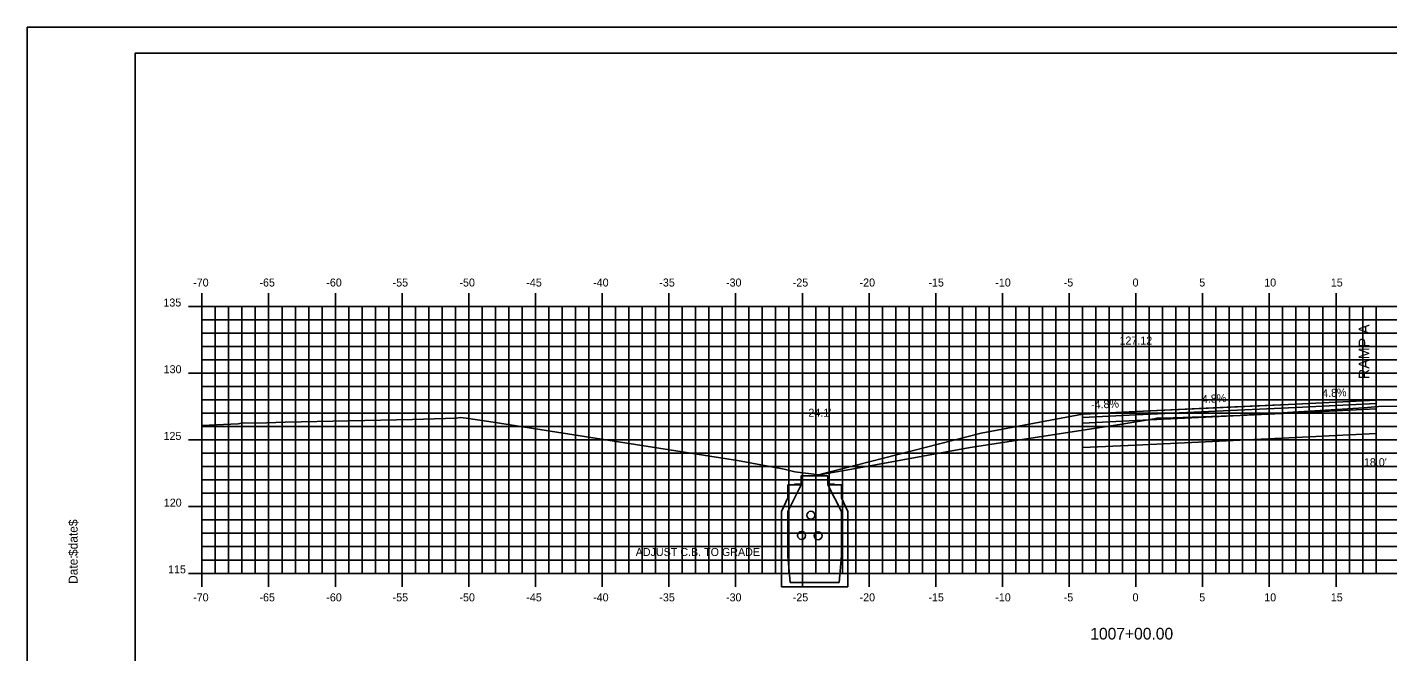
# Model space of a CAD drawing. Extents: x 851517 to 851688, y 365624 to 365734.
# Drawn here: x 851516.7 to 851618.7, y 365687.1 to 365734 of the extents above; entities that cross this region are included whole.
import ezdxf

# ---------------------------------------------------------------- set-up
doc = ezdxf.new("R2010")
doc.units = 0
for name, color, linetype in [('ANNOTATION', 7, 'Continuous'), ('BORDER', 7, 'Continuous'), ('D_Roadway_Centerline', 7, 'Continuous'), ('D_Roadway_Centerline_Text', 7, 'Continuous'), ('D_Roadway_Edge_Shoulder', 7, 'Continuous'), ('D_Roadway_Edge_TW', 7, 'Continuous'), ('D_Roadway_FinishedGrade', 7, 'Continuous'), ('D_Roadway_Pavement', 7, 'Continuous'), ('D_Roadway_SubGrade', 7, 'Continuous'), ('D_Text_Standard', 7, 'Continuous'), ('H_V ANNOTATION', 7, 'Continuous'), ('M_Roadway_Centerline', 7, 'Continuous'), ('MAJOR', 7, 'Continuous'), ('MINOR', 7, 'Continuous'), ('PLOT BOUNDARY', 7, 'Continuous'), ('S_Drainage_CB', 7, 'Continuous'), ('S_Drainage_Invert', 7, 'Continuous'), ('S_Roadway_Centerline', 7, 'Continuous')]:
    doc.layers.add(name, color=color, linetype=linetype)

msp = doc.modelspace()

# ---------------------------------------------------------------- linework, layer by layer
at = {"layer": 'BORDER'}
msp.add_lwpolyline([(851524.77, 365627.03), (851684.77, 365627.03), (851684.77, 365732.03), (851524.77, 365732.03)], close=True, dxfattribs=at)
at = {"layer": 'D_Roadway_Centerline'}
for points in [[(851595.77, 365704.96), (851598.1, 365705.07), (851599.76, 365705.15), (851599.77, 365705.15), (851606.61, 365705.48), (851611.77, 365705.72), (851611.77, 365705.72), (851617.78, 365706.01)], [(851595.77, 365704.96), (851588.17, 365703.54), (851575.68, 365700.33)]]:
    msp.add_lwpolyline(points, dxfattribs=at)
at = {"layer": 'D_Roadway_Edge_Shoulder'}
msp.add_lwpolyline([(851599.77, 365705.15), (851595.77, 365704.96), (851595.77, 365704.71), (851599.77, 365704.9)], close=True, dxfattribs=at)
at = {"layer": 'D_Roadway_Edge_TW'}
for points in [[(851599.77, 365705.15), (851611.77, 365705.72), (851611.77, 365705.47), (851599.77, 365704.9)], [(851611.77, 365705.72), (851617.78, 365706.01), (851617.78, 365705.76), (851611.77, 365705.47)]]:
    msp.add_lwpolyline(points, close=True, dxfattribs=at)
at = {"layer": 'D_Roadway_FinishedGrade'}
for p, q in [((851599.77, 365705.15), (851599.77, 365704.9)), ((851599.77, 365705.15), (851599.77, 365704.9)), ((851611.77, 365705.72), (851611.77, 365705.47)), ((851617.78, 365706.01), (851617.78, 365705.76)), ((851617.78, 365706.01), (851617.78, 365705.76)), ((851595.77, 365704.96), (851595.77, 365704.71)), ((851595.77, 365704.96), (851595.77, 365704.71))]:
    msp.add_line(p, q, dxfattribs=at)
at = {"layer": 'D_Roadway_Pavement'}
for points in [[(851599.77, 365704.9), (851611.77, 365705.47), (851611.77, 365705.06), (851599.77, 365704.48)], [(851611.77, 365705.47), (851617.78, 365705.76), (851617.78, 365705.35), (851611.77, 365705.06)], [(851599.77, 365704.9), (851595.77, 365704.71), (851595.77, 365704.29), (851599.77, 365704.48)]]:
    msp.add_lwpolyline(points, close=True, dxfattribs=at)
at = {"layer": 'D_Roadway_SubGrade'}
msp.add_line((851617.78, 365712.51), (851617.78, 365703.51), dxfattribs=at)
for points in [[(851611.77, 365705.06), (851617.78, 365705.35), (851617.78, 365703.51), (851611.77, 365703.22)], [(851599.77, 365704.48), (851595.77, 365704.29), (851595.77, 365704.79), (851595.77, 365704.96), (851595.77, 365702.46), (851599.77, 365702.65)], [(851599.77, 365704.48), (851611.77, 365705.06), (851611.77, 365703.22), (851599.77, 365702.65)]]:
    msp.add_lwpolyline(points, close=True, dxfattribs=at)
at = {"layer": 'MAJOR'}
for p, q in [((851529.77, 365714.03), (851529.77, 365713.03)), ((851534.77, 365714.03), (851534.77, 365713.03)), ((851539.77, 365714.03), (851539.77, 365713.03)), ((851544.77, 365714.03), (851544.77, 365713.03)), ((851549.77, 365714.03), (851549.77, 365713.03)), ((851554.77, 365714.03), (851554.77, 365713.03)), ((851559.77, 365714.03), (851559.77, 365713.03)), ((851564.77, 365714.03), (851564.77, 365713.03)), ((851569.77, 365714.03), (851569.77, 365713.03)), ((851574.77, 365714.03), (851574.77, 365713.03)), ((851579.77, 365714.03), (851579.77, 365713.03)), ((851584.77, 365714.03), (851584.77, 365713.03)), ((851589.77, 365714.03), (851589.77, 365713.03)), ((851594.77, 365714.03), (851594.77, 365713.03)), ((851599.77, 365714.03), (851599.77, 365713.03)), ((851604.77, 365714.03), (851604.77, 365713.03)), ((851609.77, 365714.03), (851609.77, 365713.03)), ((851614.77, 365714.03), (851614.77, 365713.03)), ((851528.76, 365713.03), (851529.77, 365713.03)), ((851529.77, 365713.03), (851669.77, 365713.03)), ((851529.77, 365693.03), (851529.77, 365713.03)), ((851529.77, 365693.03), (851529.77, 365713.03)), ((851529.77, 365713.03), (851669.77, 365713.03)), ((851534.77, 365693.03), (851534.77, 365713.03)), ((851539.77, 365693.03), (851539.77, 365713.03)), ((851544.77, 365693.03), (851544.77, 365713.03)), ((851549.77, 365693.03), (851549.77, 365713.03)), ((851554.77, 365693.03), (851554.77, 365713.03)), ((851559.77, 365693.03), (851559.77, 365713.03)), ((851564.77, 365693.03), (851564.77, 365713.03)), ((851569.77, 365693.03), (851569.77, 365713.03)), ((851574.77, 365693.03), (851574.77, 365713.03)), ((851579.77, 365693.03), (851579.77, 365713.03)), ((851584.77, 365693.03), (851584.77, 365713.03)), ((851589.77, 365693.03), (851589.77, 365713.03)), ((851594.77, 365693.03), (851594.77, 365713.03)), ((851599.77, 365693.03), (851599.77, 365713.03)), ((851604.77, 365693.03), (851604.77, 365713.03)), ((851609.77, 365693.03), (851609.77, 365713.03)), ((851614.77, 365693.03), (851614.77, 365713.03)), ((851528.76, 365708.03), (851529.77, 365708.03)), ((851529.77, 365708.03), (851669.77, 365708.03)), ((851528.76, 365703.03), (851529.77, 365703.03)), ((851529.77, 365703.03), (851669.77, 365703.03)), ((851528.76, 365698.03), (851529.77, 365698.03)), ((851529.77, 365698.03), (851669.77, 365698.03)), ((851528.76, 365693.03), (851529.77, 365693.03)), ((851529.77, 365693.03), (851669.77, 365693.03)), ((851529.77, 365693.03), (851669.77, 365693.03)), ((851529.77, 365692.02), (851529.77, 365693.03)), ((851534.77, 365692.02), (851534.77, 365693.03)), ((851539.77, 365692.02), (851539.77, 365693.03)), ((851544.77, 365692.02), (851544.77, 365693.03)), ((851549.77, 365692.02), (851549.77, 365693.03)), ((851554.77, 365692.02), (851554.77, 365693.03)), ((851559.77, 365692.02), (851559.77, 365693.03)), ((851564.77, 365692.02), (851564.77, 365693.03)), ((851569.77, 365692.02), (851569.77, 365693.03)), ((851574.77, 365692.02), (851574.77, 365693.03)), ((851579.77, 365692.02), (851579.77, 365693.03)), ((851584.77, 365692.02), (851584.77, 365693.03)), ((851589.77, 365692.02), (851589.77, 365693.03)), ((851594.77, 365692.02), (851594.77, 365693.03)), ((851599.77, 365692.02), (851599.77, 365693.03)), ((851604.77, 365692.02), (851604.77, 365693.03)), ((851609.77, 365692.02), (851609.77, 365693.03)), ((851614.77, 365692.02), (851614.77, 365693.03))]:
    msp.add_line(p, q, dxfattribs=at)
at = {"layer": 'MINOR'}
for p, q in [((851530.77, 365693.03), (851530.77, 365713.03)), ((851531.77, 365693.03), (851531.77, 365713.03)), ((851532.77, 365693.03), (851532.77, 365713.03)), ((851533.77, 365693.03), (851533.77, 365713.03)), ((851535.77, 365693.03), (851535.77, 365713.03)), ((851536.77, 365693.03), (851536.77, 365713.03)), ((851537.77, 365693.03), (851537.77, 365713.03)), ((851538.77, 365693.03), (851538.77, 365713.03)), ((851540.77, 365693.03), (851540.77, 365713.03)), ((851541.77, 365693.03), (851541.77, 365713.03)), ((851542.77, 365693.03), (851542.77, 365713.03)), ((851543.77, 365693.03), (851543.77, 365713.03)), ((851545.77, 365693.03), (851545.77, 365713.03)), ((851546.77, 365693.03), (851546.77, 365713.03)), ((851547.77, 365693.03), (851547.77, 365713.03)), ((851548.77, 365693.03), (851548.77, 365713.03)), ((851550.77, 365693.03), (851550.77, 365713.03)), ((851551.77, 365693.03), (851551.77, 365713.03)), ((851552.77, 365693.03), (851552.77, 365713.03)), ((851553.77, 365693.03), (851553.77, 365713.03)), ((851555.77, 365693.03), (851555.77, 365713.03)), ((851556.77, 365693.03), (851556.77, 365713.03)), ((851557.77, 365693.03), (851557.77, 365713.03)), ((851558.77, 365693.03), (851558.77, 365713.03)), ((851560.77, 365693.03), (851560.77, 365713.03)), ((851561.77, 365693.03), (851561.77, 365713.03)), ((851562.77, 365693.03), (851562.77, 365713.03)), ((851563.77, 365693.03), (851563.77, 365713.03)), ((851565.77, 365693.03), (851565.77, 365713.03)), ((851566.77, 365693.03), (851566.77, 365713.03)), ((851567.77, 365693.03), (851567.77, 365713.03)), ((851568.77, 365693.03), (851568.77, 365713.03)), ((851570.77, 365693.03), (851570.77, 365713.03)), ((851571.77, 365693.03), (851571.77, 365713.03)), ((851572.77, 365693.03), (851572.77, 365713.03)), ((851573.77, 365693.03), (851573.77, 365713.03)), ((851575.77, 365693.03), (851575.77, 365713.03)), ((851576.77, 365693.03), (851576.77, 365713.03)), ((851577.77, 365693.03), (851577.77, 365713.03)), ((851578.77, 365693.03), (851578.77, 365713.03)), ((851580.77, 365693.03), (851580.77, 365713.03)), ((851581.77, 365693.03), (851581.77, 365713.03)), ((851582.77, 365693.03), (851582.77, 365713.03)), ((851583.77, 365693.03), (851583.77, 365713.03)), ((851585.77, 365693.03), (851585.77, 365713.03)), ((851586.77, 365693.03), (851586.77, 365713.03)), ((851587.77, 365693.03), (851587.77, 365713.03)), ((851588.77, 365693.03), (851588.77, 365713.03)), ((851590.77, 365693.03), (851590.77, 365713.03)), ((851591.77, 365693.03), (851591.77, 365713.03)), ((851592.77, 365693.03), (851592.77, 365713.03)), ((851593.77, 365693.03), (851593.77, 365713.03)), ((851595.77, 365693.03), (851595.77, 365713.03)), ((851596.77, 365693.03), (851596.77, 365713.03)), ((851597.77, 365693.03), (851597.77, 365713.03)), ((851598.77, 365693.03), (851598.77, 365713.03)), ((851600.77, 365693.03), (851600.77, 365713.03)), ((851601.77, 365693.03), (851601.77, 365713.03)), ((851602.77, 365693.03), (851602.77, 365713.03)), ((851603.77, 365693.03), (851603.77, 365713.03)), ((851605.77, 365693.03), (851605.77, 365713.03)), ((851606.77, 365693.03), (851606.77, 365713.03)), ((851607.77, 365693.03), (851607.77, 365713.03)), ((851608.77, 365693.03), (851608.77, 365713.03)), ((851610.77, 365693.03), (851610.77, 365713.03)), ((851611.77, 365693.03), (851611.77, 365713.03)), ((851612.77, 365693.03), (851612.77, 365713.03)), ((851613.77, 365693.03), (851613.77, 365713.03)), ((851615.77, 365693.03), (851615.77, 365713.03)), ((851616.77, 365693.03), (851616.77, 365713.03)), ((851617.77, 365693.03), (851617.77, 365713.03)), ((851529.77, 365712.03), (851669.77, 365712.03)), ((851529.77, 365712.03), (851530.77, 365712.03)), ((851529.77, 365711.03), (851669.77, 365711.03)), ((851529.77, 365711.03), (851530.77, 365711.03)), ((851529.77, 365710.03), (851669.77, 365710.03)), ((851529.77, 365710.03), (851530.77, 365710.03)), ((851529.77, 365709.03), (851669.77, 365709.03)), ((851529.77, 365709.03), (851530.77, 365709.03)), ((851529.77, 365707.03), (851669.77, 365707.03)), ((851529.77, 365707.03), (851530.77, 365707.03)), ((851529.77, 365706.03), (851669.77, 365706.03)), ((851529.77, 365706.03), (851530.77, 365706.03)), ((851529.77, 365705.03), (851669.77, 365705.03)), ((851529.77, 365705.03), (851530.77, 365705.03)), ((851529.77, 365704.03), (851669.77, 365704.03)), ((851529.77, 365704.03), (851530.77, 365704.03)), ((851529.77, 365702.03), (851669.77, 365702.03)), ((851529.77, 365702.03), (851530.77, 365702.03)), ((851529.77, 365701.03), (851669.77, 365701.03)), ((851529.77, 365701.03), (851530.77, 365701.03)), ((851529.77, 365700.03), (851669.77, 365700.03)), ((851529.77, 365700.03), (851530.77, 365700.03)), ((851529.77, 365699.03), (851669.77, 365699.03)), ((851529.77, 365699.03), (851530.77, 365699.03)), ((851529.77, 365697.03), (851669.77, 365697.03)), ((851529.77, 365697.03), (851530.77, 365697.03)), ((851529.77, 365696.03), (851669.77, 365696.03)), ((851529.77, 365696.03), (851530.77, 365696.03)), ((851529.77, 365695.03), (851669.77, 365695.03)), ((851529.77, 365695.03), (851530.77, 365695.03)), ((851529.77, 365694.03), (851669.77, 365694.03)), ((851529.77, 365694.03), (851530.77, 365694.03))]:
    msp.add_line(p, q, dxfattribs=at)
at = {"layer": 'PLOT BOUNDARY'}
msp.add_lwpolyline([(851516.67, 365623.97), (851686.67, 365623.97), (851686.67, 365733.97), (851516.67, 365733.97)], close=True, dxfattribs=at)
at = {"layer": 'S_Drainage_CB'}
for p, q in [((851574.68, 365699.67), (851573.69, 365699.67)), ((851573.69, 365699.67), (851573.69, 365698.68)), ((851573.69, 365697.67), (851574.68, 365699.67)), ((851577.7, 365699.67), (851576.68, 365699.67)), ((851576.68, 365699.67), (851577.7, 365697.67)), ((851577.7, 365698.68), (851577.7, 365699.67)), ((851573.69, 365698.68), (851573.2, 365697.67)), ((851578.19, 365697.67), (851577.7, 365698.68)), ((851573.2, 365697.67), (851573.2, 365692.02)), ((851573.69, 365694.35), (851573.69, 365697.67)), ((851577.7, 365697.67), (851577.7, 365694.35)), ((851578.19, 365692.02), (851578.19, 365697.67)), ((851573.86, 365692.35), (851573.69, 365694.35)), ((851577.7, 365694.35), (851577.53, 365692.35)), ((851573.2, 365692.02), (851578.19, 365692.02)), ((851577.53, 365692.35), (851573.86, 365692.35))]:
    msp.add_line(p, q, dxfattribs=at)
msp.add_lwpolyline([(851577.17, 365699.71), (851576.68, 365699.71), (851576.68, 365700.33), (851574.68, 365700.33), (851574.68, 365699.71), (851574.19, 365699.71)], dxfattribs=at)
at = {"layer": 'S_Drainage_Invert'}
for centre in [(851575.41, 365697.38), (851574.71, 365695.87), (851575.95, 365695.85)]:
    msp.add_circle(centre, 0.3, dxfattribs=at)
at = {"layer": 'S_Roadway_Centerline'}
msp.add_lwpolyline([(851529.77, 365704.1), (851532.48, 365704.23), (851532.86, 365704.31), (851533.9, 365704.29), (851536.01, 365704.37), (851545.56, 365704.55), (851548.85, 365704.67), (851549.13, 365704.72), (851549.58, 365704.66), (851551.26, 365704.4), (851569.9, 365701.48), (851573.4, 365700.83), (851574.2, 365700.64), (851576.02, 365700.42), (851578.49, 365700.84), (851587.36, 365702.47), (851598.56, 365704.19), (851601.15, 365704.61), (851601.34, 365704.65), (851601.85, 365704.67), (851607.58, 365704.87), (851607.86, 365704.89), (851616.85, 365705.43), (851617.95, 365705.53), (851620.71, 365705.59)], dxfattribs=at)

# ---------------------------------------------------------------- texts
at = {"layer": 'ANNOTATION'}
for s, height, rotation, p in [('RAMP A', 0.8, 90, (851617.27, 365707.59)), ('4.8%', 0.6, 2.7481, (851604.73, 365705.79)), ('4.8%', 0.6, 2.7423, (851613.74, 365706.22)), ('-4.8%', 0.6, 2.7478, (851596.42, 365705.36))]:
    msp.add_text(s, height=height, rotation=rotation, dxfattribs=at).set_placement(p)
msp.add_text('ADJUST C.B. TO GRADE', height=0.6, dxfattribs=at).set_placement((851562.28, 365694.33))
at = {"layer": 'BORDER'}
for s, p in [('$date$', (851520.45, 365694.33)), ('Date:', (851520.45, 365692.24))]:
    msp.add_text(s, height=0.67, rotation=90, dxfattribs=at).set_placement(p)
at = {"layer": 'D_Roadway_Centerline'}
for s, p in [('C', (851599.76, 365705.15)), ('L', (851599.77, 365705.14))]:
    msp.add_text(s, height=0.0146, dxfattribs=at).set_placement(p)
at = {"layer": 'D_Roadway_Centerline_Text'}
msp.add_text('127.12', height=0.6, dxfattribs=at).set_placement((851598.54, 365710.18))
at = {"layer": 'D_Text_Standard'}
for s, p in [("24.1'", (851575.22, 365704.77)), ("18.0'", (851616.86, 365701.06))]:
    msp.add_text(s, height=0.6, dxfattribs=at).set_placement(p)
at = {"layer": 'H_V ANNOTATION'}
for s, height, p in [('-70', 0.6, (851529.11, 365714.53)), ('-65', 0.6, (851534.08, 365714.53)), ('-60', 0.6, (851539.09, 365714.53)), ('-55', 0.6, (851544.06, 365714.53)), ('-50', 0.6, (851549.07, 365714.53)), ('-45', 0.6, (851554.08, 365714.53)), ('-40', 0.6, (851559.09, 365714.53)), ('-35', 0.6, (851564.05, 365714.53)), ('-30', 0.6, (851569.05, 365714.53)), ('-25', 0.6, (851574.05, 365714.53)), ('-20', 0.6, (851579.06, 365714.53)), ('-15', 0.6, (851584.22, 365714.53)), ('-10', 0.6, (851589.23, 365714.53)), ('-5', 0.6, (851594.36, 365714.53)), ('0', 0.6, (851599.52, 365714.53)), ('5', 0.6, (851604.52, 365714.53)), ('10', 0.6, (851609.39, 365714.53)), ('15', 0.6, (851614.38, 365714.53)), ('135', 0.6, (851526.88, 365713.03)), ('130', 0.6, (851526.9, 365708.03)), ('125', 0.6, (851526.89, 365703.03)), ('120', 0.6, (851526.91, 365698.03)), ('115', 0.6, (851527.23, 365693.03)), ('-70', 0.6, (851529.11, 365690.93)), ('-65', 0.6, (851534.08, 365690.93)), ('-60', 0.6, (851539.09, 365690.93)), ('-55', 0.6, (851544.06, 365690.93)), ('-50', 0.6, (851549.07, 365690.93)), ('-45', 0.6, (851554.08, 365690.93)), ('-40', 0.6, (851559.09, 365690.93)), ('-35', 0.6, (851564.05, 365690.93)), ('-30', 0.6, (851569.05, 365690.93)), ('-25', 0.6, (851574.05, 365690.93)), ('-20', 0.6, (851579.06, 365690.93)), ('-15', 0.6, (851584.22, 365690.93)), ('-10', 0.6, (851589.23, 365690.93)), ('-5', 0.6, (851594.36, 365690.93)), ('0', 0.6, (851599.52, 365690.93)), ('5', 0.6, (851604.52, 365690.93)), ('10', 0.6, (851609.39, 365690.93)), ('15', 0.6, (851614.38, 365690.93)), ('1007+00.00', 0.875, (851596.35, 365688.07))]:
    msp.add_text(s, height=height, dxfattribs=at).set_placement(p)
at = {"layer": 'M_Roadway_Centerline'}
for s, p in [('C', (851617.95, 365705.53)), ('L', (851617.95, 365705.52)), ('C', (851532.86, 365704.31)), ('L', (851532.86, 365704.3))]:
    msp.add_text(s, height=0.0146, dxfattribs=at).set_placement(p)
at = {"layer": 'MAJOR'}
msp.add_text('-', height=0.006, dxfattribs=at).set_placement((851529.76, 365693.03))

doc.saveas('drawing.dxf')
